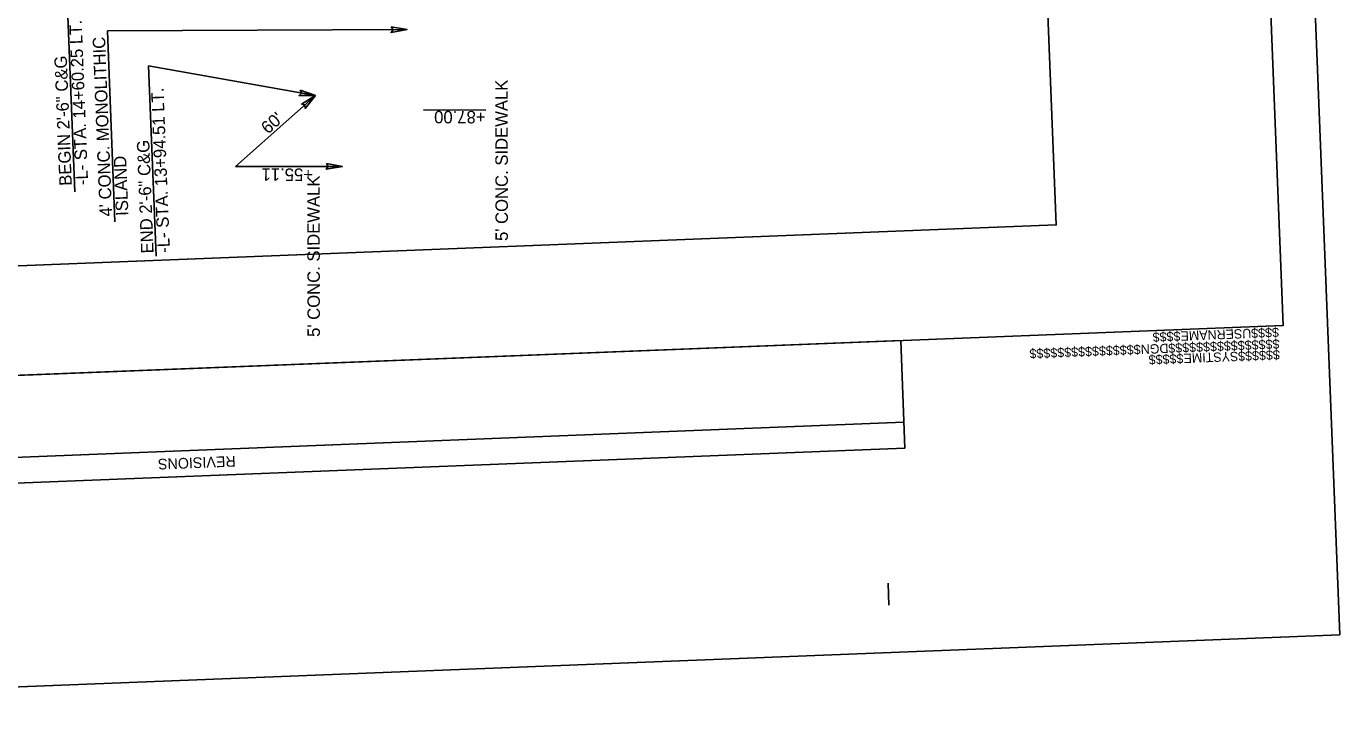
# Model space of a CAD drawing. Extents: x 1627847 to 1629013, y 761524 to 763498.
# Drawn here: x 1628275 to 1629013, y 761524 to 761909 of the extents above; entities that cross this region are included whole.
import ezdxf

# ---------------------------------------------------------------- set-up
doc = ezdxf.new("R2010")
doc.units = 0
for name, color, linetype in [('Prop Conc 2ft 6in Curb and Gutter', 7, 'Continuous'), ('Prop Dimension', 7, 'Continuous'), ('Prop Dimension Text', 7, 'Continuous'), ('Prop DSN Text', 7, 'Continuous'), ('Prop Terminator CELL', 7, 'Continuous'), ('Sheet Block Revision CELL', 7, 'Continuous'), ('Sheet Block System Information CELL', 7, 'Continuous'), ('Sheet Clip Boundary CELL', 7, 'Continuous'), ('Sheet Plan And Profile CELL', 7, 'Continuous'), ('Sheet Plot Border Outside CELL', 7, 'Continuous')]:
    doc.layers.add(name, color=color, linetype=linetype)

msp = doc.modelspace()

# ---------------------------------------------------------------- linework, layer by layer
at = {"layer": 'Prop Conc 2ft 6in Curb and Gutter'}
msp.add_line((1628436.16, 761869.13), (1628437.66, 761870.45), dxfattribs=at)
at = {"layer": 'Prop Dimension'}
for p, q in [((1628302.45, 761816.24), (1628298.18, 761924.59)), ((1628320.79, 761906.84), (1628489.23, 761907.52)), ((1628325.02, 761799.35), (1628320.79, 761906.84)), ((1628343.97, 761887.17), (1628437.66, 761870.45)), ((1628348.19, 761780.2), (1628343.97, 761887.17)), ((1628437.66, 761870.45), (1628392.82, 761830.58)), ((1628498.42, 761862.44), (1628533.42, 761862.28)), ((1628452.82, 761830.59), (1628392.82, 761830.58))]:
    msp.add_line(p, q, dxfattribs=at)
at = {"layer": 'Prop Terminator CELL'}
for points in [[(1628480.23, 761909.03), (1628489.23, 761907.52), (1628480.19, 761905.88), (1628481.33, 761907.49)], [(1628429.07, 761873.56), (1628437.66, 761870.45), (1628428.46, 761870.47), (1628429.88, 761871.84)], [(1628429.9, 761865.63), (1628437.66, 761870.45), (1628431.96, 761863.24), (1628431.75, 761865.2)], [(1628443.82, 761832.14), (1628452.82, 761830.59), (1628443.77, 761828.99), (1628444.92, 761830.59)]]:
    msp.add_lwpolyline(points, close=True, dxfattribs=at)
at = {"layer": 'Sheet Block Revision CELL'}
msp.add_line((1628768.45, 761686.66), (1627978.41, 761655.51), dxfattribs=at)
msp.add_lwpolyline([(1628769.02, 761672.13), (1627978.99, 761640.97), (1627976.6, 761701.47), (1628766.64, 761732.63)], close=True, dxfattribs=at)
at = {"layer": 'Sheet Block System Information CELL'}
msp.add_line((1628981.47, 761741.1), (1628981.47, 761741.1), dxfattribs=at)
at = {"layer": 'Sheet Clip Boundary CELL'}
msp.add_lwpolyline([(1628237.36, 761773.38), (1628231.63, 761906.6), (1628210.36, 761904.81), (1628126.56, 761769.01), (1628102.08, 762389.86), (1628829.52, 762418.55), (1628854, 761797.69)], close=True, dxfattribs=at)
at = {"layer": 'Sheet Plan And Profile CELL'}
for p, q in [((1628981.47, 761741.1), (1628981.47, 761741.1)), ((1628981.47, 761741.1), (1628981.47, 761741.1)), ((1628981.47, 761741.1), (1628981.47, 761741.1)), ((1628981.47, 761741.1), (1628981.47, 761741.1)), ((1628981.47, 761741.1), (1628981.47, 761741.1)), ((1628760, 761583.75), (1628759.5, 761596.24))]:
    msp.add_line(p, q, dxfattribs=at)
msp.add_lwpolyline([(1627873.18, 763198.56), (1627932.28, 761699.73), (1628981.47, 761741.1), (1628922.36, 763239.94)], close=True, dxfattribs=at)
at = {"layer": 'Sheet Plot Border Outside CELL'}
msp.add_lwpolyline([(1629013.34, 761567.22), (1628946.36, 763265.9), (1627847.21, 763222.56), (1627914.2, 761523.88)], close=True, dxfattribs=at)

# ---------------------------------------------------------------- texts
at = {"layer": 'Prop Dimension'}
msp.add_text('+55.11', height=7, rotation=179.74949, dxfattribs=at).set_placement((1628436.33, 761829.4))
msp.add_text('+55.11', height=7, rotation=179.74949, dxfattribs=at).set_placement((1628436.33, 761829.4))
at = {"layer": 'Prop Dimension Text'}
for s, rotation, p in [('-L- STA. 14+60.25 LT.', 92.25819, (1628309.99, 761820.2)), ('BEGIN 2\'-6" C&G', 92.25819, (1628300.82, 761819.84)), ('-L- STA. 13+94.51 LT.', 92.25819, (1628355.95, 761782.15)), ("60'", 41.64821, (1628411.01, 761848.43)), ("60'", 41.64821, (1628411.01, 761848.43)), ('+87.00', 179.74949, (1628533.31, 761861.72)), ('END 2\'-6" C&G', 92.25819, (1628346.78, 761781.79))]:
    msp.add_text(s, height=7, rotation=rotation, dxfattribs=at).set_placement(p)
at = {"layer": 'Prop DSN Text'}
for s, rotation, p in [("4' CONC. MONOLITHIC", 92.25819, (1628323.44, 761802.56)), ("5' CONC. SIDEWALK", 90.09667, (1628545.89, 761788.65)), ('ISLAND', 92.25819, (1628332.61, 761802.92)), ("5' CONC. SIDEWALK", 90.09667, (1628440.23, 761734.71))]:
    msp.add_text(s, height=7, rotation=rotation, dxfattribs=at).set_placement(p)
at = {"layer": 'Sheet Block Revision CELL'}
msp.add_text('REVISIONS', height=6, rotation=182.25819, dxfattribs=at).set_placement((1628392.75, 761667.8))
at = {"layer": 'Sheet Block System Information CELL'}
for s, p in [('$$$$USERNAME$$$$', (1628979.14, 761739.93)), ('$$$$$$$$$$$$$$$$DGN$$$$$$$$$$$$$$$$', (1628979.41, 761733.36)), ('$$$$$$SYSTIME$$$$$', (1628979.65, 761727.32))]:
    msp.add_text(s, height=5.25, rotation=182.25819, dxfattribs=at).set_placement(p)

doc.saveas('drawing.dxf')
